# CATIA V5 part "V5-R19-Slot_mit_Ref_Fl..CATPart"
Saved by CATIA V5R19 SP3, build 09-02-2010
Part number: Part2
Bounding box of the stored display mesh (mm): x 0 to 2010, y -116.842 to 366.842, z -116.842 to 116.842
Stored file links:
  \\s050023f.de050.corpintra.net\tharmen$\Data\My Documents\V5-R19-Slot_mit_Ref_Fl..CATPart
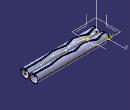
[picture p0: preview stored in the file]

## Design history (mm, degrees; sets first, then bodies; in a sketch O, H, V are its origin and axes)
AxisSystem1: origin (0, 0, 0), X (1, 0, 0), Y (0, 1, 0), Z (0, 0, 1)
Body1 (main body)
Body2
  Sketch1 on yz-plane, origin (0, 0, 0), H (0, 1, 0), V (0, 0, 1)
    circle A1 centre (0, 0) radius 116.8419
  Pad1: profile Sketch1, direction (1, 0, 0), length 2000
  Sketch2 on yz-plane, origin (0, 0, 0), H (0, 1, 0), V (0, 0, 1)
    axis line L1 (0, 200) -> (0, 60)
    point P1 (0, 200)
    point P3 (7.5, 60)
    line L2 (7.5, 60) -> (20, 150)
    point P4 (20, 150)
    point P5 (-20, 150)
    point P6 (-7.5, 60)
    line L3 (-7.5, 60) -> (-20, 150)
    line L4 (-20, 150) -> (20, 150)
    line L5 (7.5, 60) -> (-7.5, 60)
    length L5 = 15
    coincidence: P1 V
    vertical: L1 V
    symmetry: P4 P5 L1, P3 P6 L1, L2 L3 L1
    horizontal: L4 H, L5 H
  Sketch3 on xy-plane, origin (0, 0, 0), H (1, 0, 0), V (0, 1, 0)
    line L1 (290.6915, 48.0302) -> (572.073, -59.2966)
    line L2 (591.1635, -60.0667) -> (861.601, 18.8003)
    line L3 (874.8514, 19.6051) -> (1175.1486, -29.6051)
    line L4 (1183.9356, -29.7407) -> (1557.857, 19.7407)
    line L5 (1561.7926, 20) -> (2010, 20)
    line L6 (0, 0) -> (93.5271, 0)
    line L7 (101.631, 1.1153) -> (271.8961, 48.8847)
    arc A1 centre (280, 20) radius 30 from (290.6915, 48.0302) to (271.8961, 48.8847) ccw
    arc A2 centre (582.7645, -31.2664) radius 30 from (572.073, -59.2966) to (591.1635, -60.0667) ccw
    arc A3 centre (870, -10) radius 30 from (861.601, 18.8003) to (874.8514, 19.6051) cw
    arc A4 centre (1180, 0) radius 30 from (1175.1486, -29.6051) to (1183.9356, -29.7407) ccw
    arc A5 centre (1561.7926, -10) radius 30 from (1557.857, 19.7407) to (1561.7926, 20) cw
    arc A6 centre (93.5271, 30) radius 30 from (93.5271, 0) to (101.631, 1.1153) ccw
    radius A1 = 30
    radius A2 = 30 {= Sketch3.radius(A1)}
    radius A3 = 30 {= Sketch3.radius(A1)}
    radius A4 = 30 {= Sketch3.radius(A1)}
    radius A5 = 30 {= Sketch3.radius(A1)}
    radius A6 = 30 {= Sketch3.radius(A1)}
    horizontal: L5 H, L6 H
    tangency: A1 L1, A1 L7, A2 L1, A2 L2, A3 L2, A3 L3, A4 L3, A4 L4, A5 L4, A5 L5, A6 L6, A6 L7
  Set1
    Extract1: ExtractElem face of Pad1 from Sketch1.A1
    Extrude1: Element1 Sketch3, Lim1 20, Lim2 -197, Direction xy-plane
    Intersect1: ToIntersect1 Extract1, ToIntersect2 Extrude1
  Slot1: profile Sketch2, centre curve Intersect1
  Shell1: IntOffset 5, Face (start face of Pad1; end face of Pad1), ExtOffset 0
Body3
  Sketch4 on yz-plane, origin (0, 0, 0), H (0, 1, 0), V (0, 0, 1)
    circle A1 centre (0, 0) radius 116.8419
  Pad2: profile Sketch4, direction (1, 0, 0), length 2000
  Sketch5 on yz-plane, origin (0, 0, 0), H (0, 1, 0), V (0, 0, 1)
    axis line L1 (0, 200) -> (0, 60)
    point P1 (0, 200)
    point P3 (7.5, 60)
    line L2 (7.5, 60) -> (20, 150)
    point P4 (20, 150)
    point P5 (-20, 150)
    point P6 (-7.5, 60)
    line L3 (-7.5, 60) -> (-20, 150)
    line L4 (-20, 150) -> (20, 150)
    line L5 (7.5, 60) -> (-7.5, 60)
    length L5 = 15
    coincidence: P1 V
    vertical: L1 V
    symmetry: P4 P5 L1, P3 P6 L1, L2 L3 L1
    horizontal: L4 H, L5 H
  Sketch6 on xy-plane, origin (0, 0, 0), H (1, 0, 0), V (0, 1, 0)
    line L1 (290.6915, 48.0302) -> (572.073, -59.2966)
    line L2 (591.1635, -60.0667) -> (861.601, 18.8003)
    line L3 (874.8514, 19.6051) -> (1175.1486, -29.6051)
    line L4 (1183.9356, -29.7407) -> (1557.857, 19.7407)
    line L5 (1561.7926, 20) -> (2010, 20)
    line L6 (0, 0) -> (93.5271, 0)
    line L7 (101.631, 1.1153) -> (271.8961, 48.8847)
    arc A1 centre (280, 20) radius 30 from (290.6915, 48.0302) to (271.8961, 48.8847) ccw
    arc A2 centre (582.7645, -31.2664) radius 30 from (572.073, -59.2966) to (591.1635, -60.0667) ccw
    arc A3 centre (870, -10) radius 30 from (861.601, 18.8003) to (874.8514, 19.6051) cw
    arc A4 centre (1180, 0) radius 30 from (1175.1486, -29.6051) to (1183.9356, -29.7407) ccw
    arc A5 centre (1561.7926, -10) radius 30 from (1557.857, 19.7407) to (1561.7926, 20) cw
    arc A6 centre (93.5271, 30) radius 30 from (93.5271, 0) to (101.631, 1.1153) ccw
    radius A1 = 30
    radius A2 = 30 {= Sketch6.radius(A1)}
    radius A3 = 30 {= Sketch6.radius(A1)}
    radius A4 = 30 {= Sketch6.radius(A1)}
    radius A5 = 30 {= Sketch6.radius(A1)}
    radius A6 = 30 {= Sketch6.radius(A1)}
    horizontal: L5 H, L6 H
    tangency: A1 L1, A1 L7, A2 L1, A2 L2, A3 L2, A3 L3, A4 L3, A4 L4, A5 L4, A5 L5, A6 L6, A6 L7
  Slot2: profile Sketch5, centre curve Sketch6
  Shell2: IntOffset 5, Face (start face of Pad2; end face of Pad2), ExtOffset 0
  Translate1: Direction edge [YZ plane of AxisSystem1 | XY plane of AxisSystem1], ToTransfor Shell2, Length 250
